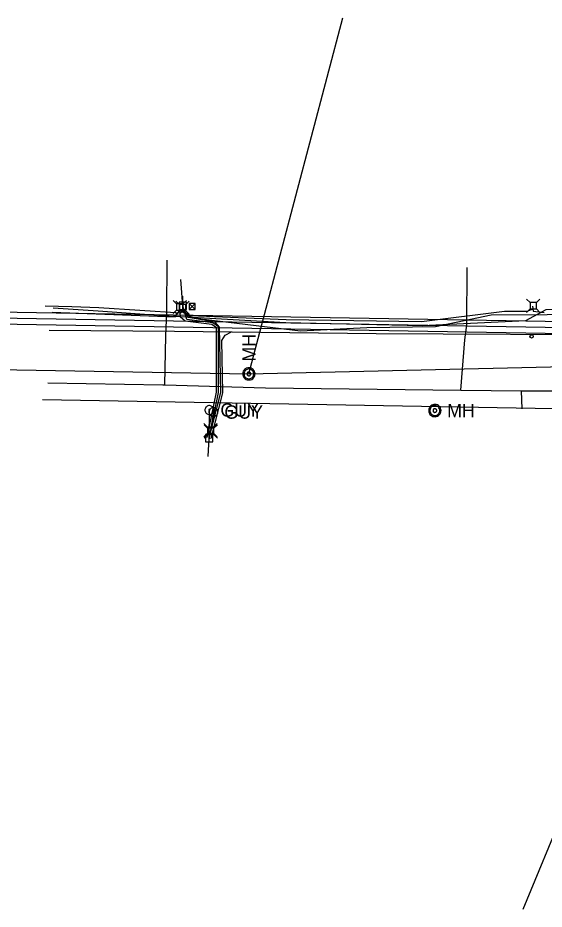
# Model space of a CAD drawing. Extents: x 600849 to 606371, y 330010 to 403088.
# Drawn here: x 603587.2 to 603848.5, y 337754.7 to 338197.2 of the extents above; entities that cross this region are included whole.
import ezdxf

# ---------------------------------------------------------------- set-up
doc = ezdxf.new("R2010")
doc.units = 0
for name, color, linetype in [('E_DRN_SS_MH', 7, 'Continuous'), ('E_MISCPROP', 7, 'Continuous'), ('E_UTL_AG_Bold', 7, 'Continuous'), ('E_UTL_E_UG', 7, 'Continuous'), ('E_UTL_EGuyWire', 7, 'Continuous'), ('E_UTL_EPowerPole', 7, 'Continuous'), ('E_UTL_ETransformer', 7, 'Continuous'), ('E_UTL_G_UG', 7, 'Continuous'), ('E_UTL_Overhead', 7, 'Continuous'), ('E_UTL_SAN', 7, 'Continuous'), ('E_UTL_SAN_UG', 7, 'Continuous'), ('E_UTL_SAN_UG_MMSD', 7, 'Continuous'), ('E_UTL_SAN_UG_OUTER_LIMITS', 7, 'Continuous'), ('E_UTL_T_UG', 7, 'Continuous'), ('E_UTL_TV_UG', 7, 'Continuous')]:
    doc.layers.add(name, color=color, linetype=linetype)

# ---------------------------------------------------------------- blocks, each defined once
blk = doc.blocks.new('ACAD_PROXY_ENTITY_18')
at = {"layer": 'E_DRN_SS_MH'}
for points in [[(1841881.9, 1030282.7), (1841881.7, 1030284.4), (1841881.2, 1030286.1), (1841880.4, 1030287.7), (1841879.3, 1030289.1), (1841877.9, 1030290.3), (1841876.4, 1030291.1), (1841874.7, 1030291.7), (1841873, 1030292), (1841871.2, 1030291.9), (1841869.5, 1030291.5), (1841867.9, 1030290.7), (1841866.4, 1030289.7), (1841865.2, 1030288.4), (1841864.3, 1030286.9), (1841863.6, 1030285.3), (1841863.3, 1030283.6), (1841863.3, 1030281.8), (1841863.6, 1030280), (1841864.3, 1030278.4), (1841865.2, 1030276.9), (1841866.4, 1030275.6), (1841867.9, 1030274.6), (1841869.5, 1030273.9), (1841871.2, 1030273.5), (1841873, 1030273.4), (1841874.7, 1030273.6), (1841876.4, 1030274.2), (1841877.9, 1030275.1), (1841879.3, 1030276.2), (1841880.4, 1030277.6), (1841881.2, 1030279.2), (1841881.7, 1030280.9), (1841881.9, 1030282.7)], [(1841880, 1030282.7), (1841879.9, 1030284.1), (1841879.5, 1030285.4), (1841878.8, 1030286.7), (1841877.9, 1030287.8), (1841876.9, 1030288.7), (1841875.6, 1030289.5), (1841874.3, 1030289.9), (1841872.9, 1030290.1), (1841871.5, 1030290), (1841870.1, 1030289.7), (1841868.8, 1030289.1), (1841867.7, 1030288.3), (1841866.7, 1030287.3), (1841865.9, 1030286.1), (1841865.4, 1030284.8), (1841865.1, 1030283.4), (1841865.1, 1030282), (1841865.4, 1030280.6), (1841865.9, 1030279.3), (1841866.7, 1030278.1), (1841867.7, 1030277), (1841868.8, 1030276.2), (1841870.1, 1030275.6), (1841871.5, 1030275.3), (1841872.9, 1030275.2), (1841874.3, 1030275.4), (1841875.6, 1030275.9), (1841876.9, 1030276.6), (1841877.9, 1030277.5), (1841878.8, 1030278.6), (1841879.5, 1030279.9), (1841879.9, 1030281.3), (1841880, 1030282.7)], [(1841875.3, 1030282.7), (1841875.3, 1030283.2), (1841875.1, 1030283.7), (1841874.9, 1030284.2), (1841874.6, 1030284.6), (1841874.2, 1030284.9), (1841873.7, 1030285.2), (1841873.2, 1030285.4), (1841872.7, 1030285.5), (1841872.1, 1030285.4), (1841871.6, 1030285.3), (1841871.1, 1030285.1), (1841870.7, 1030284.8), (1841870.3, 1030284.4), (1841870.1, 1030284), (1841869.9, 1030283.5), (1841869.8, 1030282.9), (1841869.8, 1030282.4), (1841869.9, 1030281.9), (1841870.1, 1030281.4), (1841870.3, 1030280.9), (1841870.7, 1030280.6), (1841871.1, 1030280.3), (1841871.6, 1030280), (1841872.1, 1030279.9), (1841872.7, 1030279.9), (1841873.2, 1030280), (1841873.7, 1030280.1), (1841874.2, 1030280.4), (1841874.6, 1030280.7), (1841874.9, 1030281.2), (1841875.1, 1030281.6), (1841875.3, 1030282.1), (1841875.3, 1030282.7)]]:
    blk.add_lwpolyline(points, dxfattribs=at)
blk.add_text('MH', height=20.12, dxfattribs=at).set_placement((1841891.2, 1030272.6))
blk = doc.blocks.new('ACAD_PROXY_ENTITY_8')
at = {"layer": 'E_UTL_AG_Bold'}
for points in [[(1843387.7, 1030160.5), (1843382.4, 1030165.8)], [(1843397.2, 1030160.5), (1843387.7, 1030160.5)], [(1843387.7, 1030160.5), (1843387.7, 1030151)], [(1843397.2, 1030160.5), (1843402.5, 1030165.8)], [(1843397.2, 1030151), (1843397.2, 1030160.5)], [(1843387.7, 1030151), (1843382.4, 1030145.7)], [(1843387.7, 1030151), (1843397.2, 1030151)], [(1843397.2, 1030151), (1843402.5, 1030145.7)]]:
    blk.add_lwpolyline(points, dxfattribs=at)
blk = doc.blocks.new('ACAD_PROXY_ENTITY_9')
at = {"layer": 'E_UTL_EPowerPole'}
for points in [[(1841315.4, 1030430.3), (1841304.1, 1030430.3)], [(1841304.1, 1030430.3), (1841304.1, 1030419.1)], [(1841309.8, 1030430.3), (1841309.8, 1030439.2)], [(1841315.4, 1030419.1), (1841315.4, 1030430.3)], [(1841304.1, 1030419.1), (1841315.4, 1030419.1)], [(1841310.6, 1030424.7), (1841310.6, 1030424.9), (1841310.5, 1030425), (1841310.5, 1030425.1), (1841310.4, 1030425.2), (1841310.3, 1030425.3), (1841310.2, 1030425.4), (1841310, 1030425.4), (1841309.9, 1030425.5), (1841309.7, 1030425.4), (1841309.6, 1030425.4), (1841309.5, 1030425.4), (1841309.4, 1030425.3), (1841309.3, 1030425.2), (1841309.2, 1030425.1), (1841309.2, 1030424.9), (1841309.1, 1030424.8), (1841309.1, 1030424.7), (1841309.2, 1030424.5), (1841309.2, 1030424.4), (1841309.3, 1030424.3), (1841309.4, 1030424.2), (1841309.5, 1030424.1), (1841309.6, 1030424), (1841309.7, 1030424), (1841309.9, 1030424), (1841310, 1030424), (1841310.2, 1030424.1), (1841310.3, 1030424.1), (1841310.4, 1030424.2), (1841310.5, 1030424.3), (1841310.5, 1030424.5), (1841310.6, 1030424.6), (1841310.6, 1030424.7)]]:
    blk.add_lwpolyline(points, dxfattribs=at)
blk = doc.blocks.new('ACAD_PROXY_ENTITY_11')
at = {"layer": 'E_UTL_SAN'}
for points in [[(1841308.5, 1030298.2), (1841306.7, 1030298.1), (1841305, 1030297.6), (1841303.5, 1030296.8), (1841302.1, 1030295.7), (1841300.9, 1030294.3), (1841300, 1030292.8), (1841299.5, 1030291.1), (1841299.2, 1030289.4), (1841299.3, 1030287.6), (1841299.7, 1030285.9), (1841300.4, 1030284.3), (1841301.5, 1030282.8), (1841302.7, 1030281.6), (1841304.2, 1030280.6), (1841305.9, 1030280), (1841307.6, 1030279.7), (1841309.4, 1030279.7), (1841311.1, 1030280), (1841312.8, 1030280.6), (1841314.3, 1030281.6), (1841315.5, 1030282.8), (1841316.6, 1030284.3), (1841317.3, 1030285.9), (1841317.7, 1030287.6), (1841317.8, 1030289.4), (1841317.6, 1030291.1), (1841317, 1030292.8), (1841316.1, 1030294.3), (1841314.9, 1030295.7), (1841313.5, 1030296.8), (1841312, 1030297.6), (1841310.3, 1030298.1), (1841308.5, 1030298.2)], [(1841308.5, 1030296.4), (1841307.1, 1030296.2), (1841305.7, 1030295.8), (1841304.5, 1030295.2), (1841303.4, 1030294.3), (1841302.4, 1030293.2), (1841301.7, 1030292), (1841301.3, 1030290.7), (1841301.1, 1030289.3), (1841301.1, 1030287.9), (1841301.5, 1030286.5), (1841302.1, 1030285.2), (1841302.9, 1030284), (1841303.9, 1030283.1), (1841305.1, 1030282.3), (1841306.4, 1030281.8), (1841307.8, 1030281.5), (1841309.2, 1030281.5), (1841310.6, 1030281.8), (1841311.9, 1030282.3), (1841313.1, 1030283.1), (1841314.1, 1030284), (1841315, 1030285.2), (1841315.5, 1030286.5), (1841315.9, 1030287.9), (1841315.9, 1030289.3), (1841315.7, 1030290.7), (1841315.3, 1030292), (1841314.6, 1030293.2), (1841313.6, 1030294.3), (1841312.5, 1030295.2), (1841311.3, 1030295.8), (1841309.9, 1030296.2), (1841308.5, 1030296.4)], [(1841308.5, 1030291.7), (1841308, 1030291.7), (1841307.5, 1030291.5), (1841307, 1030291.3), (1841306.6, 1030290.9), (1841306.2, 1030290.5), (1841306, 1030290.1), (1841305.8, 1030289.6), (1841305.7, 1030289.1), (1841305.7, 1030288.5), (1841305.9, 1030288), (1841306.1, 1030287.5), (1841306.4, 1030287.1), (1841306.8, 1030286.7), (1841307.2, 1030286.4), (1841307.7, 1030286.2), (1841308.2, 1030286.1), (1841308.8, 1030286.1), (1841309.3, 1030286.2), (1841309.8, 1030286.4), (1841310.2, 1030286.7), (1841310.6, 1030287.1), (1841310.9, 1030287.5), (1841311.1, 1030288), (1841311.3, 1030288.5), (1841311.3, 1030289.1), (1841311.2, 1030289.6), (1841311, 1030290.1), (1841310.8, 1030290.5), (1841310.4, 1030290.9), (1841310, 1030291.3), (1841309.5, 1030291.5), (1841309, 1030291.7), (1841308.5, 1030291.7)]]:
    blk.add_lwpolyline(points, dxfattribs=at)
blk.add_text('MH', height=20.12, rotation=90, dxfattribs=at).set_placement((1841318.6, 1030307.5))
blk = doc.blocks.new('ACAD_PROXY_ENTITY_22')
at = {"layer": 'E_UTL_EGuyWire'}
for points in [[(1843181.2, 1030365.9), (1843181, 1030367.2), (1843180.7, 1030368.4), (1843180.1, 1030369.6), (1843179.3, 1030370.6), (1843178.3, 1030371.4), (1843177.2, 1030372), (1843176, 1030372.5), (1843174.8, 1030372.6), (1843173.5, 1030372.6), (1843172.3, 1030372.3), (1843171.1, 1030371.8), (1843170.1, 1030371), (1843169.2, 1030370.1), (1843168.5, 1030369), (1843168, 1030367.8), (1843167.8, 1030366.6), (1843167.8, 1030365.3), (1843168, 1030364.1), (1843168.5, 1030362.9), (1843169.2, 1030361.8), (1843170.1, 1030360.9), (1843171.1, 1030360.1), (1843172.3, 1030359.6), (1843173.5, 1030359.3), (1843174.8, 1030359.2), (1843176, 1030359.4), (1843177.2, 1030359.8), (1843178.3, 1030360.5), (1843179.3, 1030361.3), (1843180.1, 1030362.3), (1843180.7, 1030363.5), (1843181, 1030364.7), (1843181.2, 1030365.9)], [(1843175.3, 1030365.9), (1843175.3, 1030366.1), (1843175.2, 1030366.3), (1843175.2, 1030366.4), (1843175.1, 1030366.5), (1843174.9, 1030366.6), (1843174.8, 1030366.7), (1843174.7, 1030366.8), (1843174.5, 1030366.8), (1843174.3, 1030366.8), (1843174.2, 1030366.7), (1843174, 1030366.7), (1843173.9, 1030366.6), (1843173.8, 1030366.5), (1843173.7, 1030366.3), (1843173.7, 1030366.2), (1843173.6, 1030366), (1843173.6, 1030365.9), (1843173.7, 1030365.7), (1843173.7, 1030365.6), (1843173.8, 1030365.4), (1843173.9, 1030365.3), (1843174, 1030365.2), (1843174.2, 1030365.2), (1843174.3, 1030365.1), (1843174.5, 1030365.1), (1843174.7, 1030365.1), (1843174.8, 1030365.2), (1843174.9, 1030365.3), (1843175.1, 1030365.4), (1843175.2, 1030365.5), (1843175.2, 1030365.6), (1843175.3, 1030365.8), (1843175.3, 1030365.9)]]:
    blk.add_lwpolyline(points, dxfattribs=at)
blk.add_text('GUY', height=20.12, dxfattribs=at).set_placement((1843191.2, 1030355.9))

msp = doc.modelspace()

# ---------------------------------------------------------------- linework, layer by layer
at = {"layer": 'E_MISCPROP'}
msp.add_circle((603842.25, 338039.03), 0.8, dxfattribs=at)
at = {"layer": 'E_UTL_E_UG'}
for points in [[(603682.25, 337988.58), (603686.75, 338011.2), (603686.75, 338043.74), (603683.94, 338045.83), (603671.08, 338047.43), (603669.1, 338054.21)], [(603839.32, 338046.99), (603849.47, 338052.42), (604057.26, 338054.68)], [(603604.81, 338053.24), (603627.15, 338051.8), (603659.4, 338049.36), (603720.29, 338046.02), (603787.9, 338044.47), (603839.32, 338046.99)]]:
    msp.add_lwpolyline(points, dxfattribs=at)
at = {"layer": 'E_UTL_EGuyWire'}
for p, q in [((603682.25, 337988.58), (603682.28, 338002.48)), ((603684.27, 338001.47), (603682.25, 337988.58))]:
    msp.add_line(p, q, dxfattribs=at)
at = {"layer": 'E_UTL_ETransformer'}
for p, q in [((603672.27, 338055.36), (603675.27, 338052.36)), ((603675.27, 338055.36), (603672.27, 338052.36))]:
    msp.add_line(p, q, dxfattribs=at)
msp.add_lwpolyline([(603672.27, 338052.36), (603675.27, 338052.36), (603675.27, 338055.36), (603672.27, 338055.36)], close=True, dxfattribs=at)
at = {"layer": 'E_UTL_G_UG'}
for p, q in [((603661.18, 338051.11), (603661.27, 338076.9)), ((603810.15, 338044.77), (603810.24, 338073.2)), ((603602.14, 338015.99), (603659.13, 338014.92)), ((603837.54, 338003.08), (603837.16, 338012.04))]:
    msp.add_line(p, q, dxfattribs=at)
for points in [[(603660.24, 338014.99), (603660.65, 338039.4), (603661.18, 338051.11)], [(603807.06, 338012.31), (603809.14, 338037.28), (603810.15, 338044.77)], [(603659.13, 338014.92), (603660.24, 338014.99), (603710.2, 338013.48), (603807.06, 338012.31), (603837.16, 338012.04), (603860.91, 338012.03), (603883.92, 338010.64)]]:
    msp.add_lwpolyline(points, dxfattribs=at)
at = {"layer": 'E_UTL_Overhead'}
for p, q in [((603669.1, 338054.21), (603668.04, 338067.23)), ((603681.69, 337979.47), (603682.25, 337988.58))]:
    msp.add_line(p, q, dxfattribs=at)
at = {"layer": 'E_UTL_SAN_UG'}
for p, q in [((603701.92, 338020.41), (603748.49, 338197.21)), ((603431.63, 338025.16), (603701.92, 338020.41)), ((603701.92, 338020.41), (603895.55, 338024.99)), ((603838.09, 337754.66), (603898.31, 337900.75))]:
    msp.add_line(p, q, dxfattribs=at)
at = {"layer": 'E_UTL_SAN_UG_MMSD'}
msp.add_line((603141.66, 338055.73), (604202.07, 338037.6), dxfattribs=at)
at = {"layer": 'E_UTL_SAN_UG_OUTER_LIMITS'}
for p, q in [((603141.71, 338058.73), (604202.12, 338040.6)), ((603141.61, 338052.73), (604202.02, 338034.6))]:
    msp.add_line(p, q, dxfattribs=at)
at = {"layer": 'E_UTL_T_UG'}
for p, q in [((603600.71, 338054.29), (603614.08, 338053.8)), ((603614.08, 338053.8), (603627.44, 338053.32)), ((603599.45, 338007.74), (603853.39, 338003.2))]:
    msp.add_line(p, q, dxfattribs=at)
for points in [[(603842.76, 338054.1), (603843.06, 338051.58), (603848.49, 338050.96)], [(603627.44, 338053.32), (603668.06, 338050.76), (603669, 338051.76)], [(603682.25, 337988.58), (603687.97, 338011.14), (603687.39, 338043.67), (603685.22, 338046.18), (603671.96, 338048.38), (603669, 338051.76)], [(603669, 338051.76), (603672.99, 338049.45), (603720.35, 338047.39), (603787.56, 338046.44), (603828.77, 338051.55)], [(603828.77, 338051.55), (603840.09, 338051.61), (603843.08, 338052.7)]]:
    msp.add_lwpolyline(points, dxfattribs=at)
at = {"layer": 'E_UTL_TV_UG'}
for points in [[(603602.69, 338042.21), (603664.91, 338041.66), (603765.11, 338040.43), (603898.32, 338039.89), (604013.63, 338039.78), (604114.06, 338053.03), (604129.71, 338064.26)], [(603604.27, 338051.06), (603665.39, 338048.69), (603667.58, 338052.08), (603673.87, 338048.32), (603727.54, 338041.72), (603760.53, 338043.44), (603794.48, 338043.87), (603822.16, 338049.71), (603850.03, 338049.88), (603864.37, 338050.37), (603866.29, 338052.56), (603869.2, 338050.26), (604041.63, 338052.04), (604053.93, 338052.46), (604060.19, 338052.43), (604102.72, 338060.26), (604129.71, 338064.26)], [(603681.27, 337988.78), (603685.75, 338011.3), (603685.75, 338043.24), (603683.55, 338044.87), (603670.3, 338046.52), (603667.92, 338048.53), (603667.58, 338052.08)], [(603683.22, 337988.34), (603688.97, 338011.02), (603688.51, 338036.94), (603690.18, 338039.62), (603693.32, 338041.31)]]:
    msp.add_lwpolyline(points, dxfattribs=at)

# ---------------------------------------------------------------- block references
at = {"layer": 'E_DRN_SS_MH', "xscale": 0.32808333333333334, "yscale": 0.32808333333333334}
msp.add_blockref('ACAD_PROXY_ENTITY_18', (-493.46, -16.36), dxfattribs=at)
at = {"layer": 'E_UTL_AG_Bold', "xscale": 0.32808333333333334, "yscale": 0.32808333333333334}
for p in [(-1118.76, 76.69), (-1117.34, 76.38), (-943.26, 77.31), (-1103.5, 15.56), (-1103.34, 14.92)]:
    msp.add_blockref('ACAD_PROXY_ENTITY_8', p, dxfattribs=at)
at = {"layer": 'E_UTL_EGuyWire', "xscale": 0.32808333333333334, "yscale": 0.32808333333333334}
for p in [(-1032.54, -43.41), (-1030.55, -44.43)]:
    msp.add_blockref('ACAD_PROXY_ENTITY_22', p, dxfattribs=at)
at = {"layer": 'E_UTL_EPowerPole', "xscale": 0.32808333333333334, "yscale": 0.32808333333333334}
for p in [(-433.97, -10.97), (-420.82, -76.6)]:
    msp.add_blockref('ACAD_PROXY_ENTITY_9', p, dxfattribs=at)
at = {"layer": 'E_UTL_SAN', "xscale": 0.32808333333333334, "yscale": 0.32808333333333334}
msp.add_blockref('ACAD_PROXY_ENTITY_11', (-400.72, -0.2), dxfattribs=at)

doc.saveas('drawing.dxf')
